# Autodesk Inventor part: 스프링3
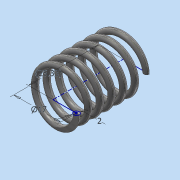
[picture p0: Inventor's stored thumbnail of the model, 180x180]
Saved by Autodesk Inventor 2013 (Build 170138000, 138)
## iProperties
Created: 2019-07
Part Number: 스프링3
Material: 강철, 탄소
Document SubType Name: Modeling
Designer: dgall
Density: 7.87 g/cm^3
Mass: -0.0170894 g
Surface Area: 20.0756 cm^2
Volume: -0.0170894 cm^3
Author: dgall
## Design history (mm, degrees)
sketch "스케치1"
  geometry: L1 (8.5, 0)-(0, 0); L2 (0, 0)-(0, 25.33); L3 (0, 25.33)-(8.5, 25.33); C1 r 1 at (8.5, 0)
  constraints: 6 end point, 2 parallel, 1 centre point, 1 coincident, 1 horizontal, 1 perpendicular
  dimensions: "d0" = 17 diameter of L1.start L2; "d2" = 25.33013 distance of L1.end L2.end (derived); "d3" = 2 diameter of C1
feature "코일1" pitch "d4" = 10; turns "d6" = 6; dims "d5" = 25.33013 (= d2), "d7" = 0, angle "d8" = 90 deg, angle "d9" = 90 deg, "d10" = 0, "d11" = 0
node "작업 평면1"
feature "분할1"
feature "분할2"
node "솔리드1"
